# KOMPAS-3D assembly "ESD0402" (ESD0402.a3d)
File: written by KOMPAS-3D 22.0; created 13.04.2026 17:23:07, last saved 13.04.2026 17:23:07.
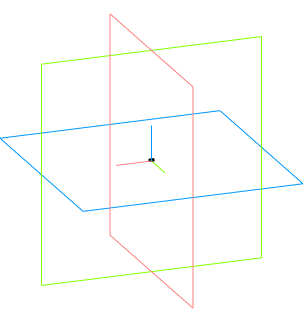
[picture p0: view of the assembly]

Document properties: Автор: Andrey; Полное имя файла: C:\Users\User1\Documents\ESD0402.a3d

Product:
- Component [assembly]: ASSEMBLY  | qty 1  | source file: ASSEMBLY_7.a3d
- Part/product: ESD0402
    Комментарий: ESD0402

Referenced files in C:\Users\User1\Documents\: ASSEMBLY_7.a3d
